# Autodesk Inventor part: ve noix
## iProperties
Author: Administrateur
Created: 2001-04
Part Number: ve noix
Material: Par défaut
Document SubType Name: Modélisation
Designer: Administrateur
Control State: 0
Master: False
Checked Out: False
PropertySet Name: Design Tracking Control
Shininess: 20.0
PropertySet Name: _Private Model Information
Length Units: 11269
Angle Units: 11283
Time Units: 11279
Mass Units: 11290
Length Display Precision: 3
Angle Display Precision: 2
Compacted: False
Density: 0.0
Volumn: 0.0
Area: 0.0
PropertySet Name: Model Information
